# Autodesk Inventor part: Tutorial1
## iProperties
Shininess: 77.0
Length Units: 11269
Angle Units: 11279
Time Units: 11290
Mass Units: 11283
Length Display Precision: 3
Angle Display Precision: 2
Created: 2001-12
Part Number: Tutorial1
Document SubType Name: Modeling
Designer: Renu Muthoo
Density: 0.0
Volumn: 0.0
Area: 0.0
PropertySet Name: Model Information
Control State: 0
Master: False
Checked Out: False
Author: Renu Muthoo
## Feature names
1. Extrusion1
2. Extrusion2
3. Fillet1
4. Hole1
5. Extrusion3
